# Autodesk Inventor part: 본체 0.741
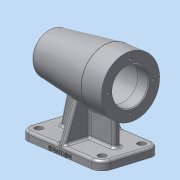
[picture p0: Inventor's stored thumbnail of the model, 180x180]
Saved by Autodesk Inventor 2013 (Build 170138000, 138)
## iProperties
Created: 2018-09
Part Number: 본체 0.741
Material: 알루미늄 6061
Document SubType Name: Modeling
Designer: Administrator
Mass: 735.723 g
Surface Area: 668.127 cm^2
Volume: 271.485 cm^3
Density: 2.71 g/cm^3
Author: Administrator
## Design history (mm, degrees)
sketch "스케치1"
  geometry: L1 (-56, 35)-(56, 35); L2 (56, 35)-(56, -35); L3 (56, -35)-(-56, -35); L4 (-56, -35)-(-56, 35); L5 (-56, 35)-(56, -35); L6 (56, 35)-(-56, -35); 1 further point
  constraints: 12 end point, 2 midpoint, 2 parallel, 1 horizontal, 1 perpendicular
  dimensions: "d0" = 112 distance of L2.end L3.end; "d1" = 70 distance of L1.end L2.end
extrude "돌출1" new body sketch "스케치1" distance "d2" = 10; taper "d3" = 0 deg
sketch "스케치2"
  geometry: L1 (-56, 0)-(56, 0) reference; L2 (-56, 74)-(56, 74); L3 (56, 74)-(56, 108); L4 (56, 108)-(28, 108); L5 (28, 108)-(-52.27, 98.144); A1 r 80 centre (24, 74) between (-52.27, 98.144) and (-56, 74); 1 further point
  constraints: 8 end point, 2 perpendicular, 2 point on circle, 1 centre point, 1 parallel, 1 point on line, 1 vertical alignment
  dimensions: "d4" = 112 distance of L2.start L2.end; "d6" = 74 distance between parallel lines of L1 L2; "d7" = 80 radius of A1; "d8" = 68 diameter of L4 L2; "d9" = 28 distance of L3.end L4.end; "d10" = 7 deg angle of L5 L4
revolve "회전1" sketch "스케치2" stored, may be unused: angle "d11" = 90 deg
sketch "스케치3"
  geometry: L1 (56, 40)-(56, 108) reference; L2 (-56, 74)-(56, 74); L3 (56, 95)-(41, 95); L4 (41, 95)-(41, 98); L5 (41, 98)-(-13, 98); L6 (-13, 98)-(-13, 95); L7 (-13, 95)-(-25, 95); L8 (-25, 95)-(-25, 91.5); L9 (-25, 91.5)-(-43, 91.5); L10 (-43, 91.5)-(-43, 90); L11 (-43, 90)-(-47, 90); L12 (-47, 90)-(-47, 84.5); L13 (-47, 84.5)-(-50, 84.5); L14 (-50, 84.5)-(-50, 74); L15 (56, 95)-(56, 74); A1 r 80 centre (24, 74) between (-52.27, 98.144) and (-52.27, 49.856) reference; 1 further point
  constraints: 28 end point, 10 parallel, 2 perpendicular, 2 point on line, 1 collinear, 1 midpoint, 1 point on circle
  dimensions: "d12" = 42 diameter of L3 L2; "d14" = 48 diameter of L5 L2; "d15" = 42 diameter of L7 L2; "d16" = 35 diameter of L9 L2; "d17" = 32 diameter of L11 L2; "d18" = 21 diameter of L13 L2; "d19" = 15 distance between parallel lines of L1 L4; "d20" = 54 distance between parallel lines of L4 L6; "d21" = 12 distance of L6.end L7.end; "d22" = 18 distance of L8.end L9.end; "d23" = 4 distance between parallel lines of L10 L12; "d24" = 3 distance between parallel lines of L12 L14
revolve "회전2" sketch "스케치3" stored, may be unused: angle "d25" = 90 deg
fillet "모깎기1" dims "d30" = 3
fillet "모깎기2" dims "d31" = 3
fillet "모깎기3" dims "d32" = 3
fillet "모깎기4" dims "d33" = 0.3
chamfer "모따기1" distance "d34" = 1; stored, may be unused: second distance "d35" = 2, angle "d36" = 45 deg
sketch "스케치9"
  geometry: L1 (56, 10)-(56, 0) reference; L2 (56, 0)-(-56, 0) reference; L3 (-56, 0)-(-56, 10) reference; L4 (-56, 10)-(56, 10) reference; L5 (-50.331, 98.382)-(27.818, 107.978) reference; L6 (28.183, 108)-(56, 108) reference; L7 (56, 108)-(56, 96) reference; L8 (56, 96)-(55, 95) reference; L9 (55, 95)-(41, 95) reference; L10 (38, 98)-(-10, 98) reference; L11 (-13, 95)-(-24.7, 95) reference; L12 (-25, 94.7)-(-25, 91.5) reference; L13 (-25, 91.5)-(-42.7, 91.5) reference; L14 (-43, 91.2)-(-43, 90) reference; L15 (-43, 90)-(-46.7, 90) reference; L16 (-47, 89.7)-(-47, 84.5) reference; L17 (-50, 81.5)-(-50, 66.5) reference; L18 (-47, 63.5)-(-47, 58.3) reference; L19 (-46.7, 58)-(-43, 58) reference; L20 (-43, 58)-(-43, 56.8) reference; L21 (-42.7, 56.5)-(-25, 56.5) reference; L22 (-25, 56.5)-(-25, 53.3) reference; L23 (-24.7, 53)-(-13, 53) reference; L24 (-10, 50)-(38, 50) reference; L25 (41, 53)-(55, 53) reference; L26 (55, 53)-(56, 52) reference; L27 (56, 52)-(56, 40) reference; L28 (56, 40)-(28.183, 40) reference; L29 (27.818, 40.022)-(-50.331, 49.618) reference; L30 (-28.115, 46.89)-(-38, 10); L31 (38, 10)-(38, 40); L32 (-38, 10)-(38, 10); A1 r 3 centre (-49.965, 95.405) between (-50.331, 98.382) and (-52.847, 96.238) reference; A2 r 3 centre (28.183, 105) between (28.183, 108) and (27.818, 107.978) reference; A3 r 3 centre (38, 95) between (41, 95) and (38, 98) reference; A4 r 3 centre (-10, 95) between (-10, 98) and (-13, 95) reference; A5 r 0.3 centre (-24.7, 94.7) between (-24.7, 95) and (-25, 94.7) reference; A6 r 0.3 centre (-42.7, 91.2) between (-42.7, 91.5) and (-43, 91.2) reference; A7 r 0.3 centre (-46.7, 89.7) between (-46.7, 90) and (-47, 89.7) reference; A8 r 3 centre (-47, 81.5) between (-47, 84.5) and (-50, 81.5) reference; A9 r 3 centre (-47, 66.5) between (-50, 66.5) and (-47, 63.5) reference; A10 r 0.3 centre (-46.7, 58.3) between (-47, 58.3) and (-46.7, 58) reference; A11 r 0.3 centre (-42.7, 56.8) between (-43, 56.8) and (-42.7, 56.5) reference; A12 r 0.3 centre (-24.7, 53.3) between (-25, 53.3) and (-24.7, 53) reference; A13 r 3 centre (-10, 53) between (-13, 53) and (-10, 50) reference; A14 r 3 centre (38, 53) between (38, 50) and (41, 53) reference; A15 r 3 centre (28.183, 43) between (27.818, 40.022) and (28.183, 40) reference; A16 r 3 centre (-49.965, 52.595) between (-52.847, 51.762) and (-50.331, 49.618) reference; A17 r 80 centre (24, 74) between (-52.847, 96.238) and (-52.847, 51.762) reference; 1 further point
  constraints: 6 end point, 4 point on line, 1 collinear, 1 perpendicular
  dimensions: "d40" = 18 distance between parallel lines of L1 L31; "d41" = 18 distance of L3.end L30.end; "d42" = 105 deg angle of L4 L30
feature "리브1" sketch "스케치9" dims "d43" = 1, "d44" = 8, "d45" = 0, "d46" = 0, "d47" = 1, "d48" = 1
fillet "모깎기6" dims "d57" = 12
fillet "모깎기8" dims "d59" = 3
sketch "스케치11"
  geometry: L1 (100, 0)-(100, 10) reference; 3 further points
  constraints: 1 other
  dimensions: "d63" = 56 distance from line of L1 point (44, 3); "d64" = 3 vertical distance of L1.start point (44, 3)
feature "엠보싱1" sketch "스케치11" dims "d0" = 112, "d1" = 70, "d65" = 0.5, "d66" = 0
sketch "스케치12"
  geometry: C1 r 34 at (0, 0) reference; 2 further points
  constraints: 1 vertical alignment
  dimensions: "d67" = 26 distance of C1.centre point (0, 26)
hole "구멍1" sketch "스케치12" at (0, 26) diameter "d68" = 3.242; stored, may be unused: countersink angle "d72" = 90 deg, drill point angle "d74" = 118 deg; dims "d69" = 8, "d70" = 4, "d71" = 2, "d73" = 11
sketch "스케치13"
  geometry: L1 (56, 23)-(56, -23) reference; L2 (44, -35)-(-44, -35) reference; L3 (-56, -23)-(-56, 23) reference; L4 (-44, 35)-(44, 35) reference; A1 r 12 centre (44, 23) between (56, 23) and (44, 35) reference; A2 r 12 centre (44, -23) between (44, -35) and (56, -23) reference; A3 r 12 centre (-44, -23) between (-56, -23) and (-44, -35) reference; A4 r 12 centre (-44, 23) between (-44, 35) and (-56, 23) reference; 5 further points
  constraints: 4 coincident
hole "구멍2" sketch "스케치13" at (-44, 23), (-44, -23), (44, -23), (44, 23) diameter "d78" = 5.5; stored, may be unused: countersink angle "d82" = 90 deg, drill point angle "d84" = 118 deg; dims "d79" = 6, "d80" = 9.5, "d81" = 5.4, "d83" = 8
fillet "모깎기12" dims "d85" = 3
sketch "스케치15"
  geometry: L1 (4.577, 35)-(4.577, 35.5) reference; L2 (4.577, 35.5)-(4.908, 35.5) reference; L3 (4.908, 35.5)-(4.908, 35) reference; L4 (4.908, 35)-(7, 35) reference; L5 (10, 32)-(10, 4) reference; L6 (10, 4)-(43.701, 4) reference; L7 (43.701, -4)-(10, -4) reference; L8 (10, -4)-(10, -32) reference; L9 (7, -35)-(0, -35) reference; L10 (0, -35)-(0, 35) reference; L11 (0, 35)-(4.577, 35) reference; L12 (50.386, 19.401)-(8.026, 34.819); C1 r 24 at (74, 0) reference; A1 r 3 centre (7, 32) between (10, 32) and (7, 35) reference; A2 r 30.562 centre (74, 0) between (43.701, -4) and (43.701, 4) reference; A3 r 3 centre (7, -32) between (7, -35) and (10, -32) reference; 1 further point
  constraints: 2 end point, 2 point on circle, 1 tangent
  dimensions: "d86" = 20 deg angle of L12 L4
extrude "돌출3" join sketch "스케치15" stored distance "d87" = 8; taper "d88" = 0 deg
fillet "모깎기13" dims "d89" = 3
fillet "모깎기14" dims "d90" = 3
fillet "모깎기15" dims "d91" = 3
fillet "모깎기16" dims "d92" = 3
node "솔리드1"
pattern_circular "원형 패턴1" dims angle "d76" = 360 deg
mirror "대칭2"
node "투영된 루프1"
node "절단 모서리 투영2"
node "절단 모서리 투영4"
